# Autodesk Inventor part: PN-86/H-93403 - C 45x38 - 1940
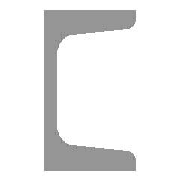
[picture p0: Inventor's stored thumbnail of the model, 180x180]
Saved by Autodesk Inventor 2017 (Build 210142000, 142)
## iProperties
_CCFamilyMember: 30
_CCFamilyDisplayName: PN-86/H-93403 - Ceownik
_FrameMemberDoc: Frame Member File
_Version: 15.0.0
_GetPNFromCC: 1
Created: 2016-02
Part Number: PN-86/H-93403 - C 45x38 - 1940
Material: Stal, miękka
Description: Ceownik
Document SubType Name: Modeling
Standard: PN
Designer: X
Standards Organization: PN
Language: pl-PL
Size Designation: C 45x38
Categories: <MemberInstance><Categories><Category DisplayName="Kształtowniki konstrukcyjne" InternalName="089c4875-fa83-4c05-b084-43b9cc11f5ed" Mnemonic="GRDR"><CategoryPar
Stock Number: C 45x38
Density: 7.85 g/cm^3
Appearance: Częściowo polerowana
IsCustomPart: 1
G_L: 1940,000 mm
G_W: 38,000 mm
G_H: 45,000 mm
Author: X
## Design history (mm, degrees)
node "Płaszczyzna początkowa"
node "Płaszczyzna końcowa"
sketch "Szkic"
  geometry: L1 (0, 0)-(0, 22.5); L2 (0, 22.5)-(38, 22.5); L3 (38, 22.5)-(38, 20.59); L4 (35.239, 17.599)-(10.522, 15.622); L5 (5, 9.641)-(5, 0); L6 (5, 0)-(0, 0); L7 (21.5, 22.5)-(21.5, 16.5); L8 (38, 17.82)-(38, 16.5); L9 (38, 16.5)-(21.5, 16.5); L10 (0, 15)-(0, -27); L11 (-5.539, 0)-(16.007, 0); L12 (0, 0)-(0, -22.5); L13 (0, -22.5)-(38, -22.5); L14 (38, -22.5)-(38, -20.59); L15 (35.239, -17.599)-(10.522, -15.622); L16 (5, -9.641)-(5, 0); L17 (0, 29.4)-(0, -36.4) reference; L18 (-10.744, 0)-(25.692, 0) reference; A1 r 6 centre (11, 9.641) between (10.522, 15.622) and (5, 9.641); A2 r 6 centre (11, -9.641) between (5, -9.641) and (10.522, -15.622); A3 r 3 centre (35, 20.59) between (35.239, 17.599) and (38, 20.59); A4 r 3 centre (35, -20.59) between (38, -20.59) and (35.239, -17.599); 5 further points
  constraints: 32 end point, 12 point on line, 8 point on circle, 8 tangent, 6 symmetric about line, 4 centre point, 4 parallel, 3 collinear, 3 perpendicular, 2 equal radius, 5 other
  dimensions: "d0" = 5 distance between parallel lines of L1 L5 (= G_T); "d1" = 22.5 distance between parallel lines of L6 L2 (= 0.5 x G_H); "d2" = 38 distance between parallel lines of L3 L1 (= G_W); "d3" = 6 distance of L2.end L8.end (= G_T1); "d4" = 16.5 distance of L7.start L2.end (= G_C); "d5" = 1.32 distance of L8.start L8.end (computed from G_NG, G_C); "d23" = 6 radius of A1 (= G_IR); "d24" = 3 radius of A3 (= G_ER); "d25" = 0 distance between parallel lines of L10 L12 (computed from ex)
extrude "Bryła" new body sketch "Szkic" stored distance "d6" = 1940 (= G_L); taper "d7" = 0 deg
node "Driven Length"
  sketch "Sketch3"
    geometry: L1 (0, 0)-(10, 0) reference
    constraints: 2 end point, 1 horizontal
  workplane "Work Plane3"
  sketch "Sketch4"
    geometry: L1 (-2, 0)-(12, 0) reference; L2 (-2, 1940)-(12, 1940) reference
    dimensions: "d29" = 1940 distance between parallel lines of L1 L2 (derived)
body "Solid1"
other parameters: "G_W" = 38 [user parameter; used in 1 equation term], "G_H" = 45 [user parameter; used in 1 equation term], "G_T" = 5 [user parameter; used in 1 equation term], "G_T1" = 6 [user parameter; used in 1 equation term], "G_NG" = 0.8 [user parameter; used in 1 equation term], "G_ER" = 3 [user parameter; used in 1 equation term], "G_IR" = 6 [user parameter; used in 1 equation term], "G_C" = 16.5 [user parameter; used in 2 equation terms], "G_L" = 1940 (= d29) [user parameter; used in 1 equation term], "ex" = 0 [user parameter; used in 1 equation term], "G_OFFSET_START" = 0 [user parameter; used in 1 equation term], "G_OFFSET_END" = 0 [user parameter; used in 1 equation term], "d26" = 0 (computed from G_OFFSET_START), "d28" = 90 deg
